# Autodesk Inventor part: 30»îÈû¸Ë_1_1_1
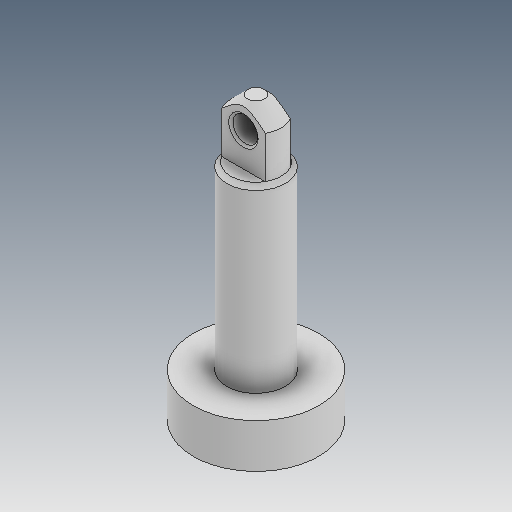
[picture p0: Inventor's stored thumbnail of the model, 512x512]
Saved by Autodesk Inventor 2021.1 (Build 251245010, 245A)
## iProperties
Created: 2019-04
Part Number: 30»îÈû¸Ë_1_1_1
Material: Ogólny
Document SubType Name: Modeling
Designer: user
Density: 1 g/cm^3
Appearance: Domyślna
Author: user
Revision Number: ÈÎºÎ
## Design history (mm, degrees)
feature "Í¹Ì¨-À­Éì1"
node "Bryła1"
